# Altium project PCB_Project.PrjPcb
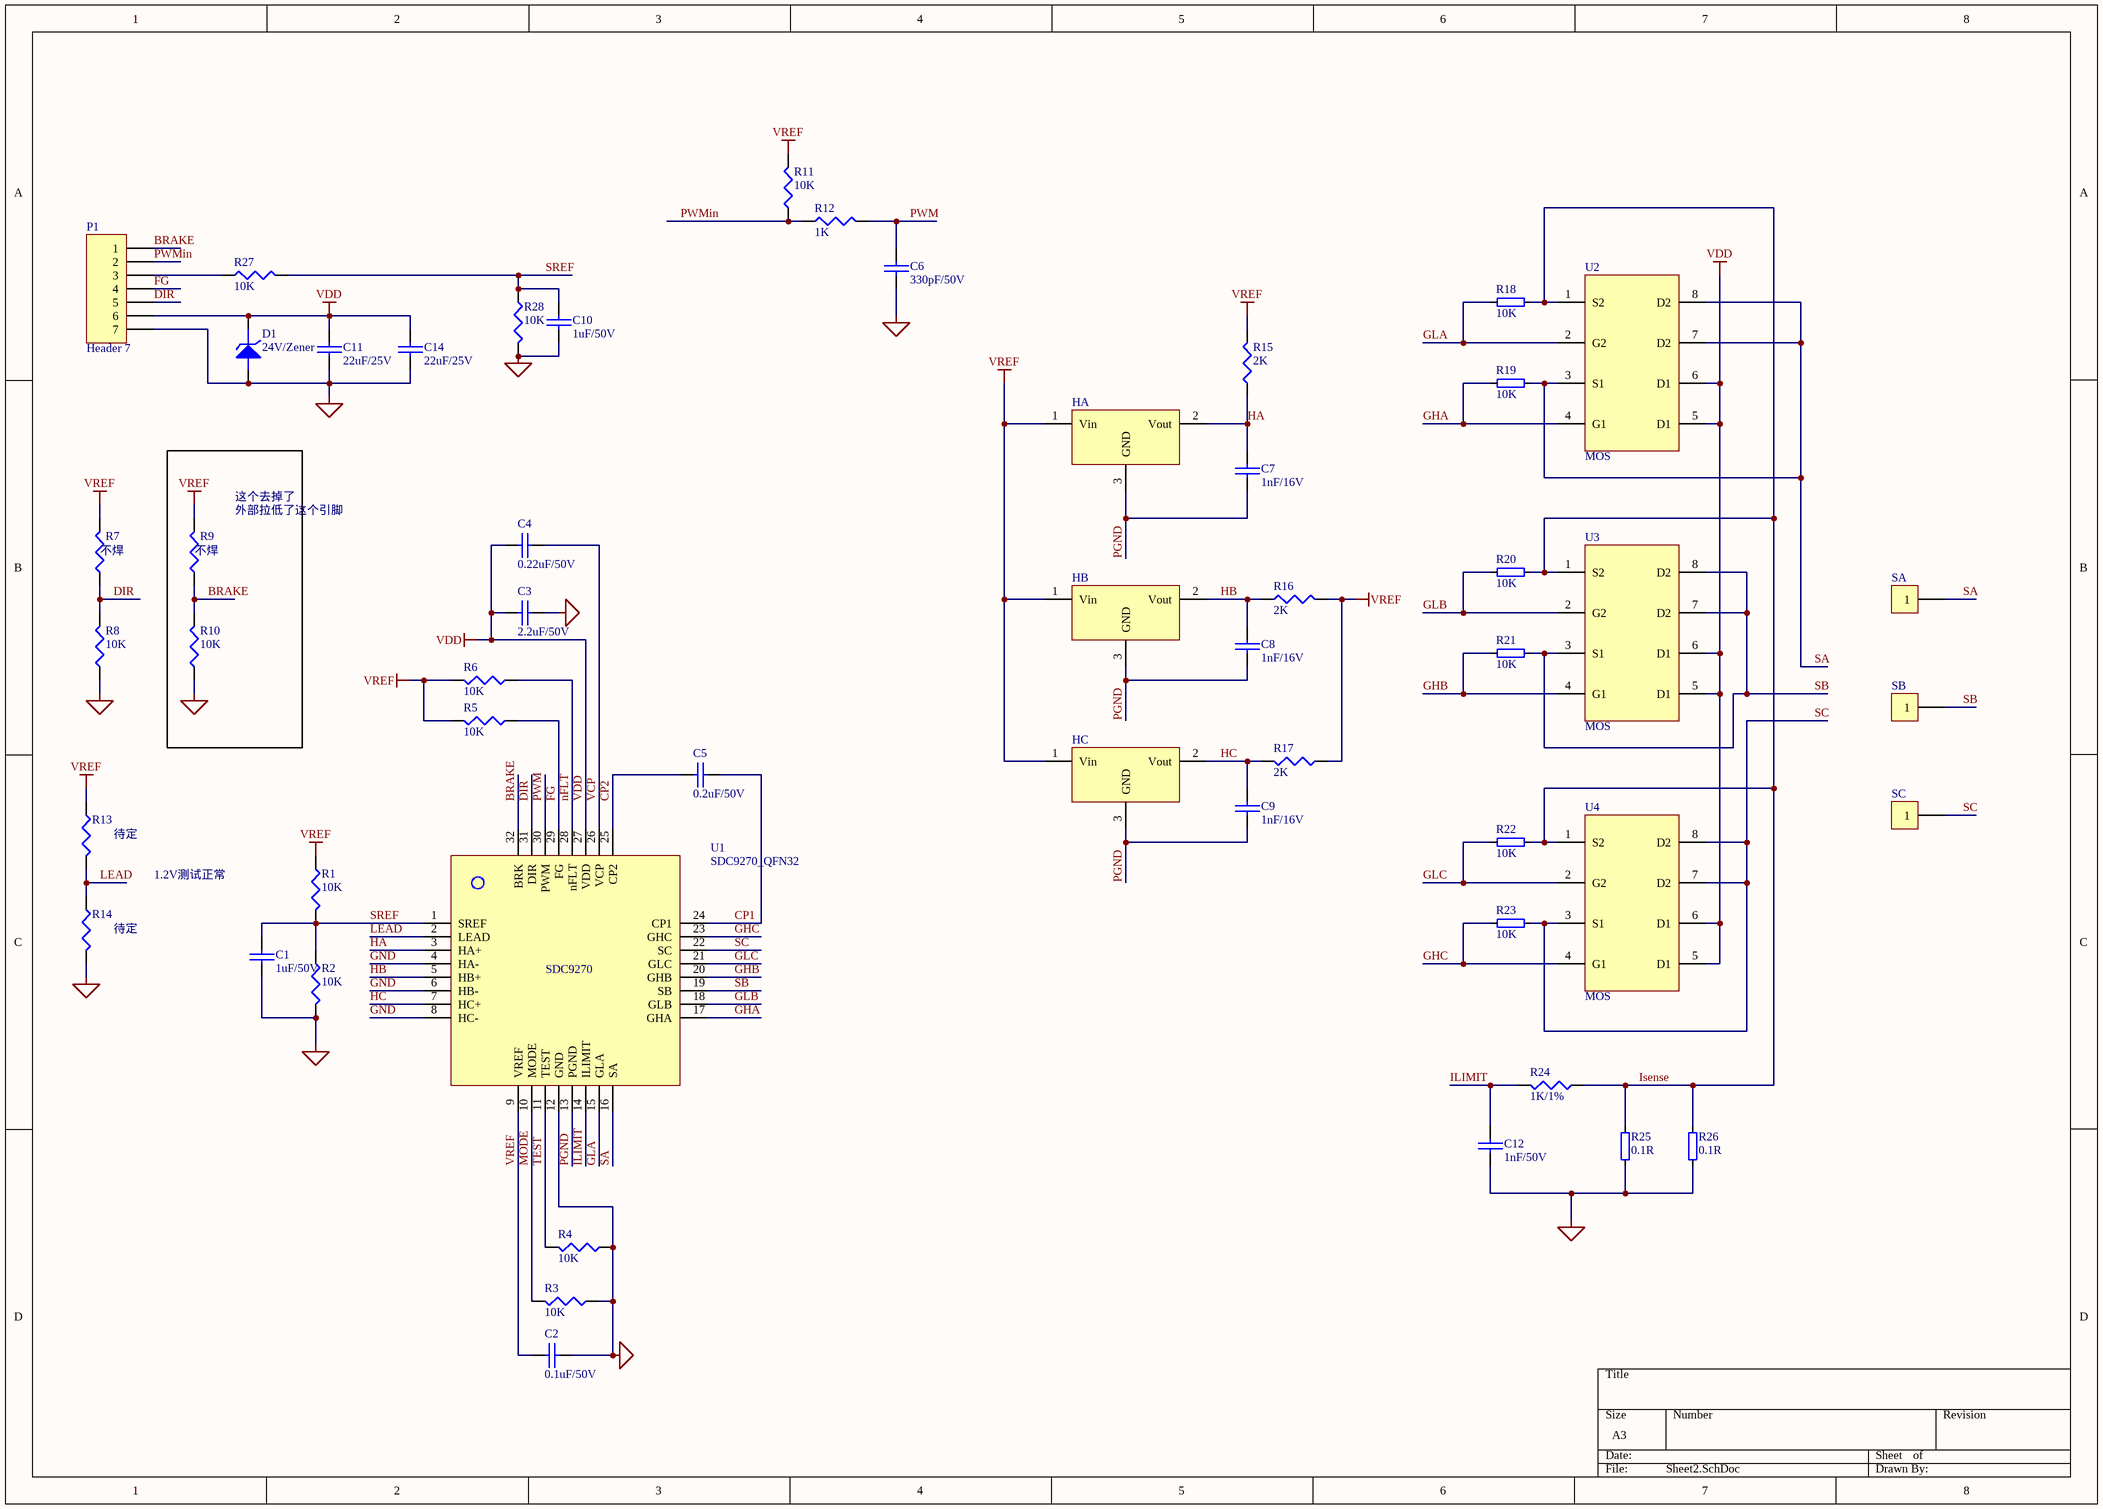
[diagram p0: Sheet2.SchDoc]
1 sheet, 53 parts. Net scope: global (net labels, ports and power ports of the same name join across sheets).
Board file: PCB1.PcbDoc

## Sheet Sheet2.SchDoc
size A3

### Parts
C1  1uF/50V  [C0603]
C2  0.1uF/50V  [C0603]
C3  2.2uF/50V  [C0603]
C4  0.22uF/50V  [C0603]
C5  0.2uF/50V  [C0603]
C6  330pF/50V  [C0603]
C7  1nF/16V  [C0603]
C8  1nF/16V  [C0603]
C9  1nF/16V  [C0603]
C10  1uF/50V  [C0603]
C11  22uF/25V  [C0603]
C12  1nF/50V  [C0603]
C14  22uF/25V  [C0603]
D1  24V/Zener  [SMB]
HA  HALL_SOT23-3  [SOT-23]  (value not drawn)
HB  HALL_SOT23-3  [SOT-23]  (value not drawn)
HC  HALL_SOT23-3  [SOT-23]  (value not drawn)
P1  Header 7  [HDR1X7]
R1  10K  [R0603]
R2  10K  [R0603]
R3  10K  [R0603]
R4  10K  [R0603]
R5  10K  [R0603]
R6  10K  [R0603]
R7  (no value)  [R0603]
R8  10K  [R0603]
R9  (no value)  [R0603]
R10  10K  [R0603]
R11  10K  [R0603]
R12  1K  [R0603]
R13  (no value)  [R0603]
R14  (no value)  [R0603]
R15  2K  [R0603]
R16  2K  [R0603]
R17  2K  [R0603]
R18  10K  [R0603]
R19  10K  [R0603]
R20  10K  [R0603]
R21  10K  [R0603]
R22  10K  [R0603]
R23  10K  [R0603]
R24  1K/1%  [R0603]
R25  0.1R  [R2512]
R26  0.1R  [R2512]
R27  10K  [R0603]
R28  10K  [R0603]
SA  (no value)  [cp1]
SB  (no value)  [cp1]
SC  (no value)  [cp1]
U1  SDC9270_QFN32  [QFN32 (5*5)]
U2  MOS  [SOP-8]
U3  MOS  [SOP-8]
U4  MOS  [SOP-8]

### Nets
SGND: C1.2 C2.1 C3.2 C6.1 C10.2 C11.1 C12.1 C14.1 D1.1(A) P1.7 R2.2 R3.1 R4.1 R8.1 R10.1 R14.2 R25.1 R26.1 R28.2 U1.12(GND)
VDD: C3.1 C4.1 C11.2 C14.2 D1.2(K) P1.6 U1.27(VDD) U2.5(D1) U2.6(D1) U3.5(D1) U3.6(D1) U4.5(D1) U4.6(D1)
VREF: C2.2 HA.1(Vin) HB.1(Vin) HC.1(Vin) R1.1 R5.2 R6.2 R7.2 R9.2 R11.2 R13.1 R15.2 R16.2 R17.1 U1.9(VREF)
BRAKE: P1.1 R9.1 R10.2 U1.32(BRK)
CP1: C5.1 U1.24(CP1)
CP2: C5.2 U1.25(CP2)
DIR: P1.5 R7.1 R8.2 U1.31(DIR)
FG: P1.4 R5.1 U1.29(FG)
GHA: R19.1 U1.17(GHA) U2.4(G1)
GHB: R21.2 U1.20(GHB) U3.4(G1)
GHC: R23.1 U1.23(GHC) U4.4(G1)
GLA: R18.2 U1.15(GLA) U2.2(G2)
GLB: R20.1 U1.18(GLB) U3.2(G2)
GLC: R22.2 U1.21(GLC) U4.2(G2)
GND: U1.4(HA-) U1.6(HB-) U1.8(HC-)
HA: C7.2 HA.2(Vout) R15.1 U1.3(HA+)
HB: C8.2 HB.2(Vout) R16.1 U1.5(HB+)
HC: C9.2 HC.2(Vout) R17.2 U1.7(HC+)
ILIMIT: C12.2 R24.2 U1.14(ILIMIT)
Isense: R18.1 R20.2 R22.1 R24.1 R25.2 R26.2 U2.1(S2) U3.1(S2) U4.1(S2)
LEAD: R13.2 R14.1 U1.2(LEAD)
MODE: R3.2 U1.10(MODE)
nFLT: R6.1 U1.28(nFLT)
PGND: C7.1 C8.1 C9.1 HA.3(GND) HB.3(GND) HC.3(GND) U1.13(PGND)
PWM: C6.2 R12.2 U1.30(PWM)
PWMin: P1.2 R11.1 R12.1
SA: R19.2 SA.1 U1.16(SA) U2.3(S1) U2.7(D2) U2.8(D2)
SB: R21.1 SB.1 U1.19(SB) U3.3(S1) U3.7(D2) U3.8(D2)
SC: R23.2 SC.1 U1.22(SC) U4.3(S1) U4.7(D2) U4.8(D2)
SREF: C1.1 C10.1 R1.2 R2.1 R27.2 R28.1 U1.1(SREF)
TEST: R4.2 U1.11(TEST)
VCP: C4.2 U1.26(VCP)
NetP1_3: P1.3 R27.1

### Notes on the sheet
- (near R9) 这个去掉了
- (near R9) 外部拉低了这个引脚
- (near R7) 不焊
- (near R9) 不焊
- (near R13) 待定
- 1.2V测试正常
- (near R14) 待定

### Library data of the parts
C1 C6-C12 C14 = C0603
C2 C4 C5 = C0805
C3 = C1206
D1 = Zener_SOD-123: Zener Diode
P1 = Header 7: Header, 7-Pin
R1-R17 R24 R27 R28 = R0603
R18-R23 = R1_0603
R25 R26 = R2512
SA SB SC = CON1: Connector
